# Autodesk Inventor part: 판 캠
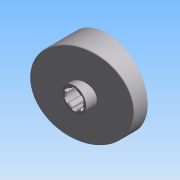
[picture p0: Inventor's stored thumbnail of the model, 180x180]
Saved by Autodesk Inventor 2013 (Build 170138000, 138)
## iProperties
Company: 한국ATC센터
Created: 2014-07
Part Number: 판 캠
Document SubType Name: 모델링
Designer: KYOUNG IL JANG
Material: 강철
Mass: 681.586 g
Surface Area: 331.301 cm^2
Volume: 86.8262 cm^3
Density: 7.85 g/cm^3
변환 표준: STEP AP214IS
파일 이름: C:\Users\SeoGD\Desktop\?쒗뿕\??stp
전처리기: Build: 253, Release: 2010 SP1 - Date: Wed 07/29/2009
전송 단위: 밀리미터
불확실성: 0.01
Author: KYOUNG IL JANG
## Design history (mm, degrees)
node "작업 평면4"
sketch "스케치1"
  geometry: C1 r 44.5 at (0, 0); 1 further point
  constraints: 1 centre point, 1 coincident
  dimensions: "d25" = 89 diameter of C1
extrude "돌출1" new body sketch "스케치1" distance "d1" = 40; taper "d2" = 0 deg
sketch "스케치2"
  geometry: L1 (-44.5, 15)-(44.5, 38.847); L2 (-44.5, 0)-(-44.5, 40) reference; L3 (-44.5, 40)-(44.5, 40) reference; L4 (44.5, 0)-(44.5, 40) reference; 1 further point
  constraints: 2 end point, 2 point on line
  dimensions: "d26" = 15 distance of L2.start L1.start; "d27" = 75 deg angle of L1 L2
extrude "돌출2" cut sketch "스케치2" stored distance "d5" = 40; taper "d6" = 0 deg
node "작업 평면1"
sketch "스케치3"
  geometry: C1 r 13 at (0, 0); 1 further point
  constraints: 1 centre point, 1 coincident
  dimensions: "d9" = 26 diameter of C1
extrude "돌출3" join sketch "스케치3" distance "d10" = 38; taper "d11" = 0 deg
hole "구멍1" diameter "d14" = 18; stored, may be unused: countersink angle "d18" = 90 deg, drill point angle "d20" = 118 deg; dims "d12" = 10, "d13" = 10, "d15" = 6, "d16" = 4, "d17" = 2, "d19" = 8
feature "쉘2" dims "d29" = 5
sketch "스케치6"
  geometry: C1 r 17.5 at (0, 0); C2 r 14 at (0, 0) reference; 1 further point
  constraints: 1 centre point, 1 coincident
  dimensions: "d28" = 35 diameter of C1
extrude "돌출4" join sketch "스케치6" stored distance "d30" = 38; taper "d31" = 0 deg
fillet "모깎기1" dims "d32" = 3
chamfer "모따기1" distance "d21" = 1; stored, may be unused: second distance "d22" = 2, angle "d23" = 45 deg
sketch "스케치7"
  geometry: L1 (-12.374, 12.374)-(-27.931, 27.931); A1 r 39.5 centre (0, 0) between (-27.931, 27.931) and (0, 39.5) reference; 2 further points
  constraints: 2 end point, 2 point on circle, 1 point on line, 1 vertical alignment, 2 other
  dimensions: "d33" = 45 deg dimension on point (0, 0) L1.start A1.end
feature "리브1" sketch "스케치7" dims "d34" = 5, "d35" = 1, "d36" = 0
fillet "모깎기2" dims "d37" = 3
sketch "스케치8"
  geometry: L1 (2.5, 10.712)-(2.5, 8.646); L2 (-2.5, 10.712)-(-2.5, 8.646); A1 r 11 centre (0, 0) between (2.5, 10.712) and (-2.5, 10.712); A2 r 9 centre (0, 0) between (2.5, 8.646) and (-2.5, 8.646) reference; 1 further point
  constraints: 4 end point, 4 point on circle, 2 parallel, 1 centre point, 1 coincident, 1 vertical
  dimensions: "d41" = 22 diameter of A1; "d42" = 5 distance between parallel lines of L1 L2
extrude "돌출5" cut sketch "스케치8" stored distance "d43" = 38; taper "d44" = 0 deg
fillet "모깎기3" dims "d48" = 1
node "솔리드1"
node "솔리드 본체"
node "곡면 본체"
pattern_circular "원형 패턴1" dims angle "d39" = 360 deg
pattern_circular "원형 패턴2" dims angle "d46" = 360 deg
node "솔리드2"
